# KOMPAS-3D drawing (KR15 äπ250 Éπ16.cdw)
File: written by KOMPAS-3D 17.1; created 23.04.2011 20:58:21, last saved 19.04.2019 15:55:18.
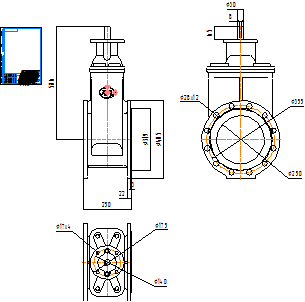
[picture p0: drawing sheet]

Sheet 1: A4, portrait

Title block, sheet 1: name: KR15 Ду250 Ру16; material: Внимание! Данный продукт является объектом авторского права ООО «Торговый Дом АДЛ». / Запрещается изменение, копирование, распространение / (в том числе путем копирования на другие сайты и ресурсы в Интернете) / или любое иное использование информации и объектов без предварительного / согласия правообладателя (ООО «Торговый Дом АДЛ»).; scale: 1:1; sheets: 1; organisation: ООО "Торговый дом АДЛ"; sheet format: A4; stored path: \\adlc.lan\data\АДЛ_ПКД\3D-модели\ADL production\Клиновые задвижки серии KR ГРАНАР\Клиновые задвижки KR15\С голым штоком\KOMPAS 2D\KR15 Ду250 Ру16.cdw

Views: Спереди 4, Проекционный вид 5, Проекционный вид 6
Dimensions and other numbers on the sheet: 250; 22; 3; 405; 319; 586; 17; 175; 140; 355; 28; 65; 30; 8; 1:1; 1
